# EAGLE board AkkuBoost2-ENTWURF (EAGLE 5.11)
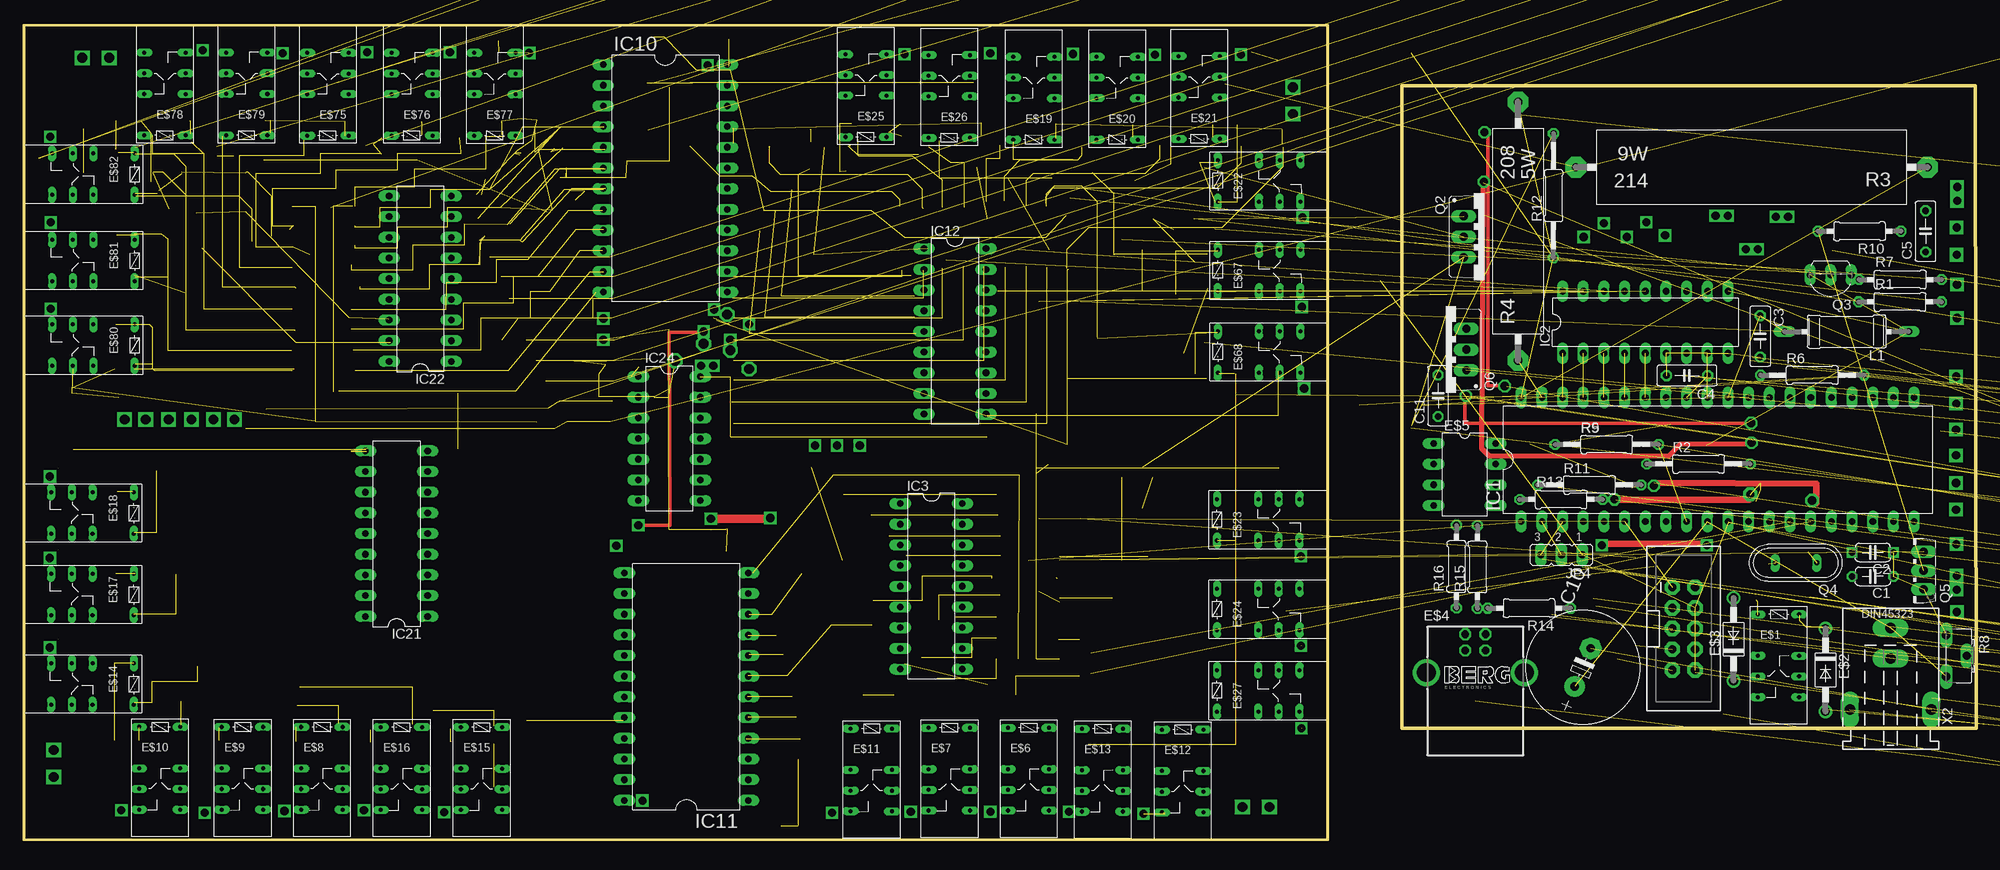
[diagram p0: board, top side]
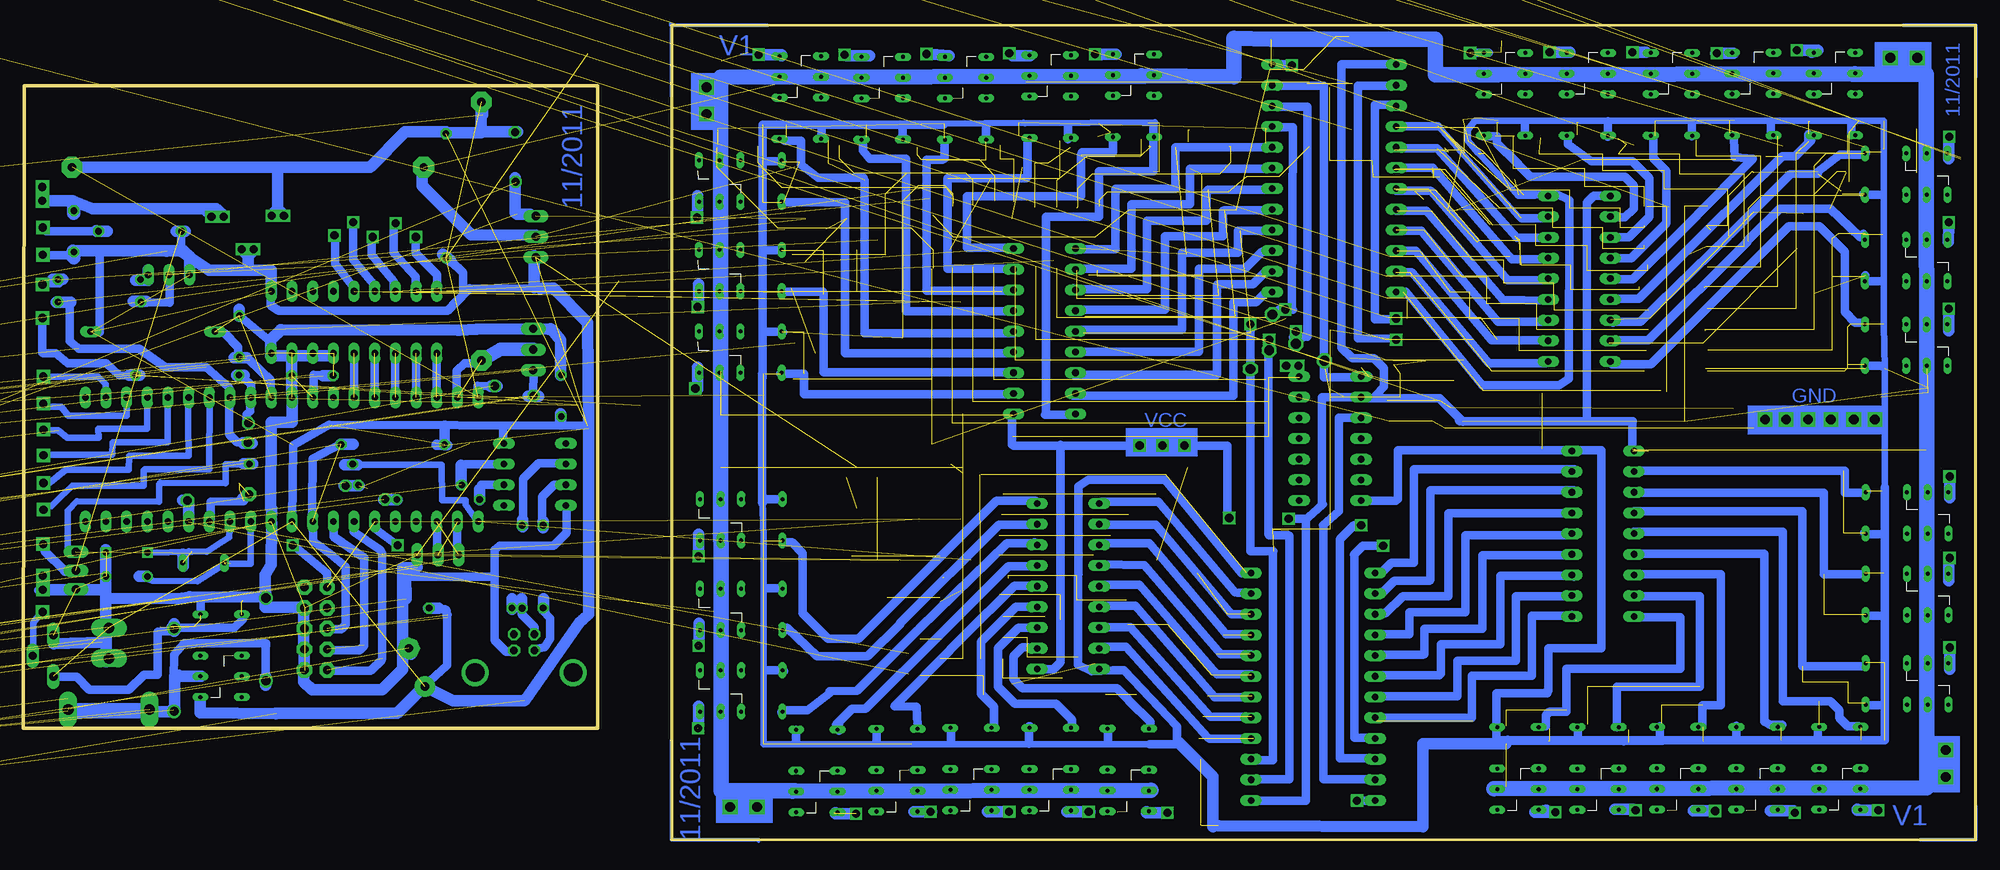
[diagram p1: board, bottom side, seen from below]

Size 239.82 x 100 mm. Coordinates in mm from the lower left corner, seen from the top.
Outline: 0.2,0 160.2,0 160.2,100
Outline: 0,0 0,100
Outline: 239.72,92.59 239.82,13.66 169.3,13.66 169.3,92.59 239.72,92.59
Outline: 0.1,100 160.1,100 160.1,0 0.1,0 0.1,100
Copper layers (1*16): Top 0.035mm / dielectric 1.5mm / Bottom 0.035mm
Design rules "default": minimum track width 10mil, minimum drill 24mil, track to track 8mil, track to pad 8mil, pad to pad 8mil, via to via 8mil, smd to smd 8mil, copper to edge 40mil, drill to drill 8mil, minimum pad ring 10mil, minimum via ring 8mil, stop-mask expansion 4mil, vias tented up to drill 0mil, thermal gap 10mil
tKeepout: 46 lines

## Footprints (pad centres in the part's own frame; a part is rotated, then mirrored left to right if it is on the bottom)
C050-024X044 = drill 0.813 octagon: 1 -2.54,0; 2 2.54,0
C050-025X075 = drill 0.813 octagon: 1 -2.54,0; 2 2.54,0
E5-13 = drill 1.016 pad 2.54 round: + -2.54,0 | drill 1.016 pad 2.54 octagon: - 2.54,0
2X5-SHROUDED_LOCK = drill 1.016 pad 1.88 octagon: 1 -1.397,5.08; 2 1.397,5.08; 3 -1.397,2.54; 4 1.397,2.54; 5 -1.397,0; 6 1.397,0; 7 -1.397,-2.54; 8 1.397,-2.54; 9 -1.397,-5.08; 10 1.397,-5.08
AXICOM-V23079-X1XXX-B301 = drill 0.5 long: 1 -6.45,-2.493; 3 -1.376,-2.493; 4 1.16,-2.493; 5 3.701,-2.493; 8 3.704,2.59; 9 1.16,2.59; 10 -1.369,2.59; 12 -6.45,2.59
DO41-10 = drill 1.118 round: A 5.08,0; C -5.08,0
PN61729-S = drill 0.95 octagon: 1 1.25,4.71; 2 -1.25,4.71; 3 -1.25,2.71; 4 1.25,2.71 | drill 2.3 pad 2.9 round: S1 -6.02,0; S2 6.02,0
DIL08 = drill 0.813 long: 1 -3.81,-3.81; 2 -1.27,-3.81; 3 1.27,-3.81; 4 3.81,-3.81; 5 3.81,3.81; 6 1.27,3.81; 7 -1.27,3.81; 8 -3.81,3.81
DIL40 = drill 0.813 long: 1 -24.13,-7.62; 2 -21.59,-7.62; 3 -19.05,-7.62; 4 -16.51,-7.62; 5 -13.97,-7.62; 6 -11.43,-7.62; 7 -8.89,-7.62; 8 -6.35,-7.62; 9 -3.81,-7.62; 10 -1.27,-7.62; 11 1.27,-7.62; 12 3.81,-7.62; 13 6.35,-7.62; 14 8.89,-7.62; 15 11.43,-7.62; 16 13.97,-7.62; 17 16.51,-7.62; 18 19.05,-7.62; 19 21.59,-7.62; 20 24.13,-7.62; 21 24.13,7.62; 22 21.59,7.62; 23 19.05,7.62; 24 16.51,7.62; 25 13.97,7.62; 26 11.43,7.62; 27 8.89,7.62; 28 6.35,7.62; 29 3.81,7.62; 30 1.27,7.62; 31 -1.27,7.62; 32 -3.81,7.62; 33 -6.35,7.62; 34 -8.89,7.62; 35 -11.43,7.62; 36 -13.97,7.62; 37 -16.51,7.62; 38 -19.05,7.62; 39 -21.59,7.62; 40 -24.13,7.62
DIL18 = drill 0.813 long: 1 -10.16,-3.81; 2 -7.62,-3.81; 3 -5.08,-3.81; 4 -2.54,-3.81; 5 0,-3.81; 6 2.54,-3.81; 7 5.08,-3.81; 8 7.62,-3.81; 9 10.16,-3.81; 10 10.16,3.81; 11 7.62,3.81; 12 5.08,3.81; 13 2.54,3.81; 14 0,3.81; 15 -2.54,3.81; 16 -5.08,3.81; 17 -7.62,3.81; 18 -10.16,3.81
DIL24-6 = drill 0.813 long: 1 -13.97,-7.62; 2 -11.43,-7.62; 3 -8.89,-7.62; 4 -6.35,-7.62; 5 -3.81,-7.62; 6 -1.27,-7.62; 7 1.27,-7.62; 8 3.81,-7.62; 9 6.35,-7.62; 10 8.89,-7.62; 11 11.43,-7.62; 12 13.97,-7.62; 13 13.97,7.62; 14 11.43,7.62; 15 8.89,7.62; 16 6.35,7.62; 17 3.81,7.62; 18 1.27,7.62; 19 -1.27,7.62; 20 -3.81,7.62; 21 -6.35,7.62; 22 -8.89,7.62; 23 -11.43,7.62; 24 -13.97,7.62
DIL14 = drill 0.813 long: 1 -7.62,-3.81; 2 -5.08,-3.81; 3 -2.54,-3.81; 4 0,-3.81; 5 2.54,-3.81; 6 5.08,-3.81; 7 7.62,-3.81; 8 7.62,3.81; 9 5.08,3.81; 10 2.54,3.81; 11 0,3.81; 12 -2.54,3.81; 13 -5.08,3.81; 14 -7.62,3.81
JP2 = drill 0.914 long: 1 -2.54,0; 2 0,0; 3 2.54,0
SMCC12 = drill 0.813 long: 1 -6.35,0; 2 8.89,0
TO220BV = drill 1.016 long: D 0,-2.54; G -2.54,-2.54; S 2.54,-2.54
TO92-EBC = drill 0.813 long: B 0,-1.27; C -2.54,-1.27; E 2.54,-1.27
QS = drill 0.61 long: 1 -2.54,0; 2 2.54,0
TO126AV = drill 1.016 long: B 2.286,-1.27; C 0,-1.27; E -2.286,-1.27
0207/10 = drill 0.813 octagon: 1 -5.08,0; 2 5.08,0
0207/12 = drill 0.813 octagon: 1 -6.35,0; 2 6.35,0
KH214-8 = drill 1.016 pad 2.54 octagon: 1 -21.59,0; 2 21.59,0
KH208-8 = drill 1.016 pad 2.54 octagon: 1 -15.875,0; 2 15.875,0
CA6H = drill 1.016 long: A -2.54,0; E 2.54,0; S 0,2.54
0207/15 = drill 0.813 octagon: 1 -7.62,0; 2 7.62,0
737992-5 = drill 1.3 pad 2.184 long: + 0,10; -1 5,0; -2 -5,0; K 0,6.25

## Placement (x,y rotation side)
C1  22p  [C050-024X044]  227.12,32.32 180 top
C2  22p  [C050-024X044]  227.12,35.25 180 top
C3  100n  [C050-025X075]  213.29,61.81 270 top
C4  100n  [C050-025X075]  204.3,56.98 180 top
C5  100n  [C050-025X075]  233.61,74.69 90 top
C10  1000µF  [E5-13]  191.48,21.16 67.2 top
C11  100n  [C050-025X075]  173.74,54.51 90 top
CON1  ISP  [2X5-SHROUDED_LOCK]  203.88,25.92 0 top
E$1  [AXICOM-V23079-X1XXX-B301]  215.47,21.22 270 top
E$2  1N4007  [DO41-10]  221.3,20.84 270 top
E$3  1N4007  [DO41-10]  210.01,24.6 90 top
E$4  [PN61729-S]  178.3,20.53 0 top
E$5  Attiny45  [DIL08]  176.99,44.85 270 top
E$6  [AXICOM-V23079-X1XXX-B301]  123.37,7.29 270 top
E$7  [AXICOM-V23079-X1XXX-B301]  113.64,7.29 270 top
E$8  [AXICOM-V23079-X1XXX-B301]  36.57,7.39 270 top
E$9  [AXICOM-V23079-X1XXX-B301]  26.84,7.39 270 top
E$10  [AXICOM-V23079-X1XXX-B301]  16.66,7.39 270 top
E$11  [AXICOM-V23079-X1XXX-B301]  104.06,7.19 270 top
E$12  [AXICOM-V23079-X1XXX-B301]  142.29,7.07 270 top
E$13  [AXICOM-V23079-X1XXX-B301]  132.45,7.16 270 top
E$14  [AXICOM-V23079-X1XXX-B301]  7.09,19.17 180 top
E$15  [AXICOM-V23079-X1XXX-B301]  56.19,7.37 270 top
E$16  [AXICOM-V23079-X1XXX-B301]  46.35,7.36 270 top
E$17  [AXICOM-V23079-X1XXX-B301]  7.09,30.17 180 top
E$18  [AXICOM-V23079-X1XXX-B301]  7.09,40.17 180 top
E$19  [AXICOM-V23079-X1XXX-B301]  124.13,92.41 90 top
E$20  [AXICOM-V23079-X1XXX-B301]  134.36,92.41 90 top
E$21  [AXICOM-V23079-X1XXX-B301]  144.44,92.51 90 top
E$22  [AXICOM-V23079-X1XXX-B301]  153.11,80.83 0 top
E$23  [AXICOM-V23079-X1XXX-B301]  153.01,39.23 0 top
E$24  [AXICOM-V23079-X1XXX-B301]  153.01,28.23 0 top
E$25  [AXICOM-V23079-X1XXX-B301]  103.51,92.73 90 top
E$26  [AXICOM-V23079-X1XXX-B301]  113.75,92.64 90 top
E$27  [AXICOM-V23079-X1XXX-B301]  153.01,18.23 0 top
E$67  [AXICOM-V23079-X1XXX-B301]  153.11,69.83 0 top
E$68  [AXICOM-V23079-X1XXX-B301]  153.11,59.83 0 top
E$75  [AXICOM-V23079-X1XXX-B301]  37.43,92.91 90 top
E$76  [AXICOM-V23079-X1XXX-B301]  47.76,92.91 90 top
E$77  [AXICOM-V23079-X1XXX-B301]  57.94,92.91 90 top
E$78  [AXICOM-V23079-X1XXX-B301]  17.41,92.93 90 top
E$79  [AXICOM-V23079-X1XXX-B301]  27.45,92.94 90 top
E$80  [AXICOM-V23079-X1XXX-B301]  7.19,60.77 180 top
E$81  [AXICOM-V23079-X1XXX-B301]  7.19,71.17 180 top
E$82  [AXICOM-V23079-X1XXX-B301]  7.19,81.77 180 top
IC1  MEGA32  [DIL40]  208.07,46.68 0 top
IC2  ULN2803  [DIL18]  199.19,63.54 0 top
IC3  ULN2803  [DIL18]  111.49,31.11 270 top
IC10  4514N  [DIL24-6]  78.8,81.21 270 top
IC11  4514N  [DIL24-6]  81.4,18.79 90 top
IC12  ULN2803  [DIL18]  114.39,62.41 270 top
IC21  ULN2803  [DIL18]  45.81,37.59 90 top
IC22  ULN2803  [DIL18]  48.71,68.89 90 top
IC24  4011N  [DIL14]  79.31,49.25 270 top
JP4  UserSwitch  [JP2]  188.89,34.99 180 top
L1  100µH  [SMCC12]  225.18,62.39 180 top
Q2  IRF5305  [TO220BV]  179.42,74.03 270 top
Q3  BC558A  [TO92-EBC]  221.93,68.09 180 top
Q4  8MHz  [QS]  217.68,33.99 180 top
Q5  BD139  [TO126AV]  232.08,33.04 90 top
Q6  IRL1004  [TO220BV]  174.65,60.19 90 top
R1  10k  [0207/10]  230.46,66.04 0 top
R2  1k  [0207/12]  205.71,46.14 0 top
R3  1R8  [KH214-8]  212.24,82.57 180 top
R4  R51  [KH208-8]  183.55,74.72 90 top
R5  10k  [0207/12]  194.43,48.54 0 top
R6  180  [0207/12]  219.69,57.04 0 top
R7  180  [0207/10]  230.49,68.78 0 top
R8  10k  [CA6H]  236.11,22.58 270 top
R9  10k  [0207/12]  194.43,48.54 0 top
R10  6  [0207/10]  225.49,74.72 180 top
R11  10k  [0207/12]  192.32,43.56 0 top
R12  500k  [0207/15]  187.89,79.08 90 top
R13  470  [0207/10]  188.85,41.77 0 top
R14  1k5  [0207/10]  184.89,28.43 180 top
R15  68  [0207/10]  178.55,33.5 90 top
R16  68  [0207/10]  175.98,33.52 90 top
X2  [737992-5]  229.3,16 0 top

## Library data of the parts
C1-C5 C10 C11 R2 R5 R9 R11 = rcl
CON1 = SparkFun
E$1 E$6-E$27 E$67 E$68 E$75-E$82 = Relais
E$2 E$3 = ref-packages-longpad
E$4 = con-berg
E$5 = atmel
IC1 = atmel; OC_FARNELL: unknown; OC_NEWARK: unknown
IC2 IC3 IC12 IC21 IC22 = uln-udn
IC10 IC11 = 45xx
IC24 = 40xx
JP4 = jumper
L1 = inductors
Q2 Q5 Q6 = transistor-power
Q3 = transistor-pnp
Q4 = special
R1 R6 R7 R10 R12-R16 = resistor
R3 R4 = resistor-power; OC_FARNELL: unknown; OC_NEWARK: unknown
R8 = pot
X2 = con-conrad

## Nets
GND: C1.1 C2.1 C3.2 C4.2 CON1.4 CON1.6 CON1.8 CON1.10 IC1.11 IC1.31 IC2.6 IC2.7 IC2.8 IC2.9 JP4.1 Q5.E R8.A
N$1: Q2.G R1.2
N$2: C1.2 IC1.12 Q4.2
N$3: C2.2 IC1.13 Q4.1
N$4: R3.2
N$5: R6.1
N$6: Q3.B
N$8: R7.2
N$9: IC1.29 R6.2
N$10: IC1.40 R3.1 R4.2 R12.1
N$11: IC1.39 R4.1
N$12: CON1.1 IC1.6
N$13: CON1.5 IC1.9 R5.2
N$16: R7.1
N$17: R8.S
N$18: IC1.1
N$19: Q5.B
N$20: IC1.26
N$22: IC1.22
N$23: IC1.27
N$24: IC1.25
N$25: IC1.24
N$26: Q5.C R10.2
N$27: R10.1
N$28: IC2.18
N$29: IC2.17
N$30: IC2.16
N$31: IC2.15
N$32: IC2.14
N$53: C3.1 IC1.30 L1.2
N$54: C4.1 IC1.32
N$55: IC1.2 JP4.2
N$56: IC1.3 JP4.3
N$57: IC1.15
N$58: IC1.14
N$75: CON1.9 IC1.7
N$76: CON1.7 IC1.8
N$114: IC1.23
N$119: C10.- X2.-1
PA2: IC1.38 IC2.1
PA3: IC1.37 IC2.2
PA4: IC1.36 IC2.3
PA5: IC1.35 IC2.4
PA6: IC1.34 IC2.5
S$173: IC1.28
S$187: Q2.D
S$188: R1.1
S$189: Q3.C
VCC: C10.+ IC1.10 IC2.10 L1.1 Q2.S Q3.E R5.1 R8.E R12.2 X2.+

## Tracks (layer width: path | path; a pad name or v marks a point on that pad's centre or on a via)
GND  (via drill 0.8 pad 1.27)  (16 unrouted)
  Bottom 1.422: IC1.31 206.78,51.27 209.35,51.27 209.41,40.69 209.34,40.64 209.34,38.95 IC1.11
  other vias: 229.66,35.25
N$1  (2 unrouted)
N$2  (2 unrouted)
  Bottom 0.813: 214.33,33.89 211.88,33.89 IC1.12 | 215,33.89 218.38,31.72 223.94,31.77 225.55,32.33 225.6,32.33
  Bottom 1.422: 225.6,32.33 C1.2
N$3  (1 unrouted)
  Bottom 0.813: IC1.13 214.51,37.15 217.26,35.35 219.49,35.39 219.12,35.34 C2.2
N$4  (1 unrouted)
N$6  (1 unrouted)
N$7  (4 unrouted)
N$8  (1 unrouted)
N$9  (3 unrouted)
N$10  (4 unrouted)
N$11  (2 unrouted)
N$12  (2 unrouted)
N$13  (3 unrouted)
  Bottom 1.016: 200.22,26.38 200.19,33.55 202.14,35.08 204.22,36.65 IC1.9
N$18  (1 unrouted)
N$19  (1 unrouted)
N$21  (via drill 1 pad 1.68)
  other vias: 237.44,27.97
N$26  (1 unrouted)
N$28  (1 unrouted)
N$29  (1 unrouted)
N$30  (1 unrouted)
N$31  (1 unrouted)
N$32  (1 unrouted)
N$53  (3 unrouted)
N$54  (1 unrouted)
N$55  (1 unrouted)
N$56  (1 unrouted)
N$57  (1 unrouted)
N$58  (1 unrouted)
N$67  (2 unrouted)
N$68  (via drill 0.8 pad 1.27)
  other vias: 224.58,35.25
N$69  (via drill 1 pad 1.68)
  other vias: 237.41,30.71 237.41,32.41
N$71  (2 unrouted)
N$72  (6 unrouted)
N$73  (2 unrouted)
N$75  (2 unrouted)
  Bottom 1.016: 195.74,22.2 195.75,35.19 195.96,35.58 199.22,37.82 IC1.7
N$76  (2 unrouted)
  Bottom 1.016: 197.95,23.88 197.96,34.64 201.7,37.18 IC1.8
N$77  (2 unrouted)
  Bottom 1.422: 229.69,35.44 229.7,32.71
N$78
  Bottom 1.016: 196.61,38.99 196.61,38.5 196.6,38.18 193.95,36.19
N$80  (2 unrouted)
N$81  (1 unrouted)
  Bottom 1.422: 199.32,48.57 200.84,48.57
N$82
  Bottom 1.016: 200.76,48.62 204.29,46.75 204.33,40.86 204.38,39.19 204.3,39.12
N$83  (1 unrouted)
N$84  (4 unrouted)
N$85  (4 unrouted)
N$86  (8 unrouted)
N$87  (1 unrouted)
N$88  (2 unrouted)
N$90  (2 unrouted)
N$91  (2 unrouted)
N$92  (2 unrouted)
N$93  (2 unrouted)
N$94  (3 unrouted)
N$95  (1 unrouted)
N$96  (4 unrouted)
N$97  (5 unrouted)
N$98  (via drill 1 pad 1.68)
  other vias: 219.65,41.65
N$99  (via drill 1 pad 1.68)
  other vias: 212.07,42.43
N$100  (2 unrouted)
N$101
  Bottom 1.422: 220.24,41.68 219.5,41.66 219.48,39.17
N$102  (4 unrouted)
N$103  (6 unrouted)
N$104  (4 unrouted)
N$105  (2 unrouted)
N$106  (4 unrouted)
N$107  (2 unrouted)
N$108  (3 unrouted)
N$109  (3 unrouted)
  Bottom 1.016: 204.13,54.24 204.14,57.07
N$110  (1 unrouted)
N$111  (2 unrouted)
N$112  (2 unrouted)
N$113  (2 unrouted)
N$115  (11 unrouted)
N$116  (2 unrouted)
N$117  (1 unrouted)
N$118  (1 unrouted)
N$119  (1 unrouted)
N$120  (2 unrouted)
N$121  (3 unrouted)
  Bottom 1.93: 234.45,15.85 224.44,15.85 224.31,15.98
N$122  (1 unrouted)
N$123  (2 unrouted)
N$124  (2 unrouted)
N$125  (3 unrouted)
N$126  (2 unrouted)
N$127  (4 unrouted)
N$128  (11 unrouted)
N$129  (2 unrouted)
N$130  (4 unrouted)
N$131  (2 unrouted)
N$132  (4 unrouted)
N$133  (3 unrouted)
N$134  (2 unrouted)
N$135  (1 unrouted)
N$136  (2 unrouted)
N$137  (2 unrouted)
N$138  (via drill 1 pad 1.68)
  other vias: 237.39,36.29
N$139  (6 unrouted)
N$140
  Bottom 1.422: 220.17,33.59 220.18,34.99 220.22,35.02
N$141  (2 unrouted)
N$142  (4 unrouted)
  Bottom 1.016: 209.39,54.26 209.44,56.4 212.03,58.86
  Bottom 1.422: 212.36,59.16 213.93,59.15
N$143  (1 unrouted)
N$144  (1 unrouted)
N$145  (2 unrouted)
N$146  (via drill 1 pad 1.68)
  other vias: 237.33,40.53
N$147  (4 unrouted)
N$148  (2 unrouted)
N$149  (3 unrouted)
N$150  (4 unrouted)
N$151  (via drill 1 pad 1.68)
  other vias: 237.33,43.79
N$152  (via drill 1 pad 1.68)
  other vias: 237.34,47.19
N$153  (via drill 1 pad 1.68)
  other vias: 237.34,50.35 237.35,53.55
N$154  (via drill 1 pad 1.68)  (1 unrouted)
  other vias: 237.35,56.87 237.46,64.07 237.46,68.17 237.41,71.83 237.48,78.45 237.41,75.17 237.48,80.15
N$156  (1 unrouted)
  Bottom 1.422: 209.37,39.06 209.35,39.06
N$157
  Bottom 0.813: 238.62,22.48 238.62,26.66 237.55,28
N$158
  Bottom 1.422: 229.67,32.37 229.62,21.86
N$159  (3 unrouted)
  Bottom 1.422: 234.37,17.38 234.37,15.76
N$160  (2 unrouted)
  Bottom 1.422: 236.06,24.07 230.15,24.27 | 229.19,26.13 229.12,26.06
N$161  (2 unrouted)
PA2  (1 unrouted)
PA3  (1 unrouted)
PA4  (1 unrouted)
PA5  (1 unrouted)
PA6  (1 unrouted)
S$1  (1 unrouted)
S$2  (2 unrouted)
S$3  (5 unrouted)
S$4
  Bottom 0.813: 223.09,43.56 223.1,41.52 233.17,41.54
S$5
  Bottom 1.016: 233.46,30.7 229.77,30.7 229.67,30.6
S$6
  Bottom 1.016: 237.96,30.64 237.13,30.72 236.54,30.74 233.42,30.74 233.37,30.79
S$7
  Bottom 1.016: 237.27,36.29 237.19,35.4 234.79,33.06 234.74,32.92 232.91,32.92
S$8
  Bottom 0.813: 234.38,35.34 234.36,40.41 233.24,41.54
  Bottom 1.016: 233.25,35.27 233.58,35.27 234.38,35.34
S$9  (5 unrouted)
S$10
  Bottom 0.813: 216.95,54.3 216.96,45.48 224.9,45.5 225,45.39 225.01,43.46 233.81,43.45 235.88,41.45 236.39,40.91 237.71,40.89
  Bottom 1.016: 217.05,54.3 216.95,54.3
S$11
  Bottom 0.813: 219.54,54.26 219.54,50.78 219.52,47.13 226.83,47.12 226.86,45.45 234.58,45.45 236.54,43.85
S$12
  Bottom 0.813: 222.06,54.21 222.06,50.84 222.05,48.78 228.85,48.81 228.87,47.28 237.34,47.29
S$13  (2 unrouted)
  Bottom 0.813: 224.6,54.21 224.6,51.47 224.6,50.48 230.6,50.48 230.57,49.34 234.42,49.34 235.47,50.22
S$14
  Bottom 0.813: 227.14,53.46 227.14,52.05 233.31,52.03 234.32,52.03 235.13,53.15 236.9,53.19
  Bottom 1.016: 227.16,54.19 227.14,53.46
S$15
  Bottom 0.813: 237.3,50.28 235.53,50.28
S$16
  Bottom 0.813: 229.67,54.3 229.67,55.91 230.63,56.87 237.36,56.87
S$17  (2 unrouted)
S$18
  Bottom 0.813: 184,39.01 185.5,41.13 185.5,41.7 188.4,41.7 188.44,46.05 198.99,46.03
S$19
  Bottom 0.813: 211.52,46.08 214.94,46.08 214.94,43.8 222.98,43.81 223.12,43.67
S$20  (4 unrouted)
S$21
  Bottom 1.016: 213.58,57.02 213.08,57 212.59,56.61 211.83,55.85 211.81,54.05 211.84,54.02
S$22  (2 unrouted)
  Bottom 1.016: 225.42,56.99 228.03,57.01 229.63,58.48 234.36,58.51 235.85,59.74 237.35,59.74
S$23  (2 unrouted)
S$24  (1 unrouted)
  Bottom 1.016: 214.48,54.08 214.48,55.28 214.45,55.31 214.57,55.55 217.34,57.99
S$25  (1 unrouted)
  Bottom 1.016: 226.16,66 221.83,65.96 221.85,69.39 221.92,69.46
S$26  (3 unrouted)
S$27  (2 unrouted)
S$28  (1 unrouted)
  Bottom 1.016: 235.42,68.94 235.38,68.3 237.32,68.3 237.35,68.26
S$29
  Bottom 1.016: 216.7,62.25 215.1,62.2 213.4,60.5 213.4,59.15 213.36,59.12
S$30
  Bottom 1.016: 237.58,71.75 233.56,71.75 233.48,71.66
S$31
  Bottom 1.676: 233.66,72.2 233.69,71.5 233.65,71.45
S$32
  Bottom 1.676: 233.65,78.14 233.65,76.95 233.6,76.91
S$33
  Bottom 1.422: 219.4,69.21 219.4,71.62 220.11,72.34 233.73,72.34 233.77,72.38
S$34
  Bottom 1.422: 219.9,74.68 221.04,74.68 221.06,74.7
S$35
  Bottom 1.016: 230.59,74.72 236.98,74.72 237.42,75.16
  Bottom 1.422: 229.54,74.72 230.59,74.72 230.81,74.72 230.84,74.75
S$36
  Bottom 1.016: 220.39,74.73 220.39,72.69 220.14,72.44
S$37
  Bottom 1.422: 237.54,78.45 233.81,78.45 233.52,78.15
S$38  (3 unrouted)
  Bottom 1.422: 222.14,72.3 222.19,72.26
S$39  (2 unrouted)
S$40  (1 unrouted)
S$41  (2 unrouted)
S$42  (1 unrouted)
S$43  (1 unrouted)
S$44  (4 unrouted)
S$45  (1 unrouted)
  Bottom 1.016: 229.69,29.66 229.76,29.1
  Bottom 1.422: 219.5,29.78 220.86,29.57 229.69,29.66
S$46  (3 unrouted)
  Bottom 1.676: 221.39,15.93 221.33,15.87
S$47
  Bottom 1.422: 221.23,17.52 221.25,17.52 221.25,15.74 224.27,15.74 224.27,15.75
S$48
  Bottom 1.422: 217.99,20.06 221.24,20.06 221.24,15.83
S$49  (4 unrouted)
S$50  (4 unrouted)
S$51
  Bottom 1.422: 210.07,18.96 210.07,20.01 210.04,20.03
S$52
  Bottom 1.422: 210.07,30.37 210.07,29.05 210.09,29.02
S$53  (3 unrouted)
  Bottom 1.422: 210.01,29.78 219.37,29.8
S$54  (1 unrouted)
  Bottom 1.422: 218.09,17.26 218.09,15.76 218.11,15.56 208.73,15.48
S$55  (2 unrouted)
S$56  (1 unrouted)
  Bottom 1.422: 205.37,26.48 205.33,20.54
S$57
  Bottom 1.422: 205.29,28.54 210.09,28.54 210.11,30.09
S$58
  Bottom 1.422: 209.34,38.85 209.39,33.75 210.11,32.56 210.11,29.73
S$59  (2 unrouted)
S$60
  Bottom 1.422: 205.37,28.69 205.37,25.77 205.32,25.72
S$61  (2 unrouted)
S$62
  Bottom 1.016: 202.71,23.23 198.51,23.23 197.96,23.79
S$63
  Bottom 1.016: 202.61,25.84 200.75,25.84 200.21,26.37
S$64
  Bottom 1.016: 202.64,20.73 197.13,20.73 195.81,22.04
S$65  (via drill 1)
  other vias: 206.74,36.16
S$66  (via drill 1)
  other vias: 193.82,36.16
S$67
  Top 0.813: 193.81,36.32 206.71,36.32 206.75,36.27
S$68
  Bottom 1.016: 202.53,30.94 202.48,32.7 206.75,36.2
S$69  (1 unrouted)
  Bottom 1.422: 205.37,20.74 205.37,19.42 204.33,18.38 195.75,18.38 193.21,20.92 193.25,33.41
S$70  (2 unrouted)
  Bottom 1.422: 191.47,33.44 193.18,33.41
S$71  (1 unrouted)
  Bottom 1.016: 186.56,38.99 186.54,38.21 186.54,35.46 186.54,34.49
S$72
  Bottom 1.016: 188.98,38.95 188.98,37.59 188.96,34.71
S$73
  Bottom 1.016: 221.56,25.74 221.06,25.59 223.33,25.56 223.33,20.22 224.97,20.22 226.84,18.43 231.7,18.43 233.28,20.01 235.99,20.01 236.05,19.95
S$74
  Bottom 1.422: 208.81,15.52 193.91,15.52 190.49,18.94
S$75
  Bottom 1.422: 192.19,22.79 192.19,23.74 192.48,24.04
S$76
  Bottom 1.016: 210.05,19.59 210.02,23.24 210,24.11 220.06,24.11 221.3,22.72 221.31,19.87 220.64,20.38
S$77
  Bottom 1.422: 198.73,46.07 200.36,46.07
S$78  (1 unrouted)
  Bottom 1.422: 211.64,46.16 212.75,46.15
S$79
  Bottom 1.27: 187.74,48.46 189.07,48.47
S$80
  Bottom 1.27: 188.07,48.46 188.06,50.83
S$81  (3 unrouted)
  Bottom 1.016: 193.11,28.66 193.14,28.69
S$82  (1 unrouted)
S$83  (1 unrouted)
  Bottom 1.422: 192.81,29.57 192.84,32.4
S$84  (6 unrouted)
  Bottom 1.016: 187.74,27.34 187.76,21.45 190.6,18.81
S$85  (1 unrouted)
  Bottom 1.422: 193.87,41.77 195.56,41.77
S$86  (2 unrouted)
S$87  (6 unrouted)
S$88  (3 unrouted)
  Bottom 1.016: 212.75,41.56 216.81,41.5 216.81,39.36 216.85,39.31
S$89
  Bottom 1.422: 212.08,42.51 212.94,41.81 211.99,42.56
S$90  (via drill 1)
  other vias: 200.22,43.46
S$91  (1 unrouted)
S$92  (2 unrouted)
S$93  (1 unrouted)
  Bottom 1.422: 200.44,43.49 198.56,43.49
S$94  (1 unrouted)
  Bottom 1.422: 186.06,45.95 186.02,43.55 | 183.75,41.76 183.75,43.02
S$95  (6 unrouted)
S$96  (via drill 1)
  other vias: 195.37,41.78
S$97  (1 unrouted)
  Top 0.813: 220.17,41.67 220.2,41.3 220.2,43.71 200.31,43.81 | 211.97,41.77 195.41,41.71
S$98  (2 unrouted)
S$99  (2 unrouted)
S$100  (2 unrouted)
S$101  (2 unrouted)
S$102  (2 unrouted)
S$103  (1 unrouted)
S$104  (2 unrouted)
S$105  (2 unrouted)
S$106  (2 unrouted)
S$107  (2 unrouted)
S$108  (2 unrouted)
S$109  (4 unrouted)
S$110  (4 unrouted)
S$111  (2 unrouted)
S$112
  Bottom 1.016: 173.1,40.8 173.1,37.7 174.7,36.1 181.3,36.1 181.9,35.6 181.9,32.3 192.9,32.3 193,32.4
S$113  (via drill 1)
  other vias: 181.9,55.7
S$114  (1 unrouted)
S$115
  Bottom 1.422: 182.4,55.7 181.6,55.7
S$116  (8 unrouted)
S$117  (3 unrouted)
  Bottom 1.422: 190.48,18.81 190.48,18.75 187.02,17.09 178.3,17.09
S$118  (6 unrouted)
  Bottom 1.422: 202.98,56.97 201.75,56.97
S$119  (4 unrouted)
S$120
  Bottom 1.016: 213.38,64.38 209.48,61.21 209.43,59.59 209.35,59.6 209.48,59.48
S$121
  Bottom 1.016: 204.16,57.02 203.35,57.02 203.3,56.98
S$122
  Bottom 1.422: 209.41,59.41 201.91,59.41 201.89,59.44
S$123
  Bottom 1.422: 206.87,59.42 206.87,54.69
S$124  (2 unrouted)
S$125
  Bottom 1.016: 189,59.69 189.02,59.69 189.02,53.81
S$126
  Bottom 1.016: 191.56,59.75 191.58,59.75 191.58,54.2
S$127
  Bottom 1.016: 194.11,59.75 194.15,59.75 194.15,54.06
S$128
  Bottom 1.016: 196.66,54.22 196.63,54.22 196.63,59.99
S$129
  Bottom 1.016: 199.22,59.79 199.2,59.79 199.2,54.14
S$130
  Bottom 1.422: 213.31,65.1 213.31,64.28
S$131
  Bottom 1.422: 220.36,72.19 217,69.9 209.38,69.9 209.38,67.12
S$132  (6 unrouted)
S$133  (3 unrouted)
  Bottom 1.016: 221.71,26.14 221.73,26.13
S$134  (2 unrouted)
S$135
  Bottom 1.016: 183.69,58.51 185.62,58.51 186.58,57.56 186.58,54.09 186.51,54.02
S$136  (2 unrouted)
S$137  (via drill 1)
  other vias: 212.16,51.16
S$138  (via drill 1)
  other vias: 177.15,54.51
S$139  (1 unrouted)
  Top 0.406: 212.26,51.16 177,51.16 177,54.49 177,54.45
S$140
  Bottom 1.016: 211.94,54.26 211.94,52.62 212.35,52.21 212.35,51.13 212.18,50.95
S$141  (1 unrouted)
  Bottom 1.016: 177.22,54.46 177.16,57.73
S$142
  Bottom 1.016: 209.44,66.93 209.44,65.62 208.46,64.97 187.73,64.97 186.58,66.09
S$143
  Bottom 1.422: 209.46,60.06 209.42,61.37 208.12,62.6
S$144
  Bottom 1.016: 186.39,62.57 186.27,62.57
  Bottom 1.422: 208.18,62.6 186.39,62.57 | 186.27,62.57 184.12,62.67 175.04,62.72
S$145  (1 unrouted)
  Bottom 1.422: 176.54,54.44 177.78,54.43
S$146
  Bottom 1.676: 177.19,60.2 181.22,60.2 183.92,58.63
S$147  (2 unrouted)
S$148  (5 unrouted)
  Bottom 1.016: 183.99,54.25 184,55.73 182.44,55.66 182.19,55.66
S$149  (4 unrouted)
S$150  (2 unrouted)
S$151  (8 unrouted)
S$152  (2 unrouted)
S$153  (4 unrouted)
S$154  (4 unrouted)
S$155  (via drill 1)
  other vias: 212.22,48.73
S$156
  Bottom 1.016: 214.56,54.09 214.56,49.76 213.56,48.77 212.26,48.77 212.17,48.68
S$157
  Bottom 1.422: 211.7,48.68 212.78,48.68 212.83,48.73
S$158  (via drill 1)
  other vias: 179.35,80.79
S$159  (3 unrouted)
  Top 0.61: 212.36,48.54 203.38,48.54 202.02,47.05 180,47.1 179.08,48.02 179.28,80.65
S$160  (6 unrouted)
S$161  (1 unrouted)
  Bottom 1.422: 177.56,76.8 179.17,76.8
S$162
  Bottom 1.016: 176.78,67.62 185.02,67.69 186.82,65.83
S$163  (2 unrouted)
S$164  (8 unrouted)
S$165  (via drill 1)
  other vias: 179.43,86.87
S$166  (1 unrouted)
S$167
  Top 0.406: 179.85,87.2 179.85,55.76 181.8,55.72
S$168  (2 unrouted)
S$169  (2 unrouted)
S$170  (2 unrouted)
S$171  (6 unrouted)
S$172  (2 unrouted)
S$173  (1 unrouted)
S$174  (4 unrouted)
S$175  (1 unrouted)
  Bottom 0.813: 14.16,12.23 14.29,12.23
S$176  (1 unrouted)
S$177  (1 unrouted)
  Bottom 0.813: 23.94,12.23 24.06,12.23
S$178  (1 unrouted)
S$179
  Bottom 1.93: 59.21,6.26 6,6.39
S$180  (via drill 1)
  Bottom 1.422: 34.7,3.52 v32.03,3.52
S$181  (via drill 1)
  other vias: 22.25,3.32
S$182  (2 unrouted)
S$183  (via drill 1)
  Bottom 1.422: 14.54,3.72 14.54,3.6 v12,3.6
S$184  (3 unrouted)
S$185  (3 unrouted)
S$186  (via drill 1)
  other vias: 3.22,44.6 3.22,23.6 3.22,34.6
S$187  (1 unrouted)
S$188  (1 unrouted)
S$189  (1 unrouted)
S$190
  Bottom 1.422: 25.22,3.52 22.42,3.52
S$191  (1 unrouted)
S$192  (1 unrouted)
S$193  (1 unrouted)
S$194  (1 unrouted)
S$195  (1 unrouted)
S$196  (2 unrouted)
S$197  (1 unrouted)
S$198  (1 unrouted)
S$199  (1 unrouted)
S$200  (1 unrouted)
S$201  (1 unrouted)
S$202  (2 unrouted)
S$203  (via drill 1)
  Bottom 1.422: 52.77,3.6 54.17,3.37 v51.63,3.37
S$204  (via drill 1)
  other vias: 41.78,3.62
S$205
  Bottom 1.422: 44.31,3.72 42.16,3.72
S$206  (1 unrouted)
  Bottom 0.813: 43.24,11.98 33.46,12.11
S$207
  Bottom 1.016: 84.4,37.4 86.8,37.4
S$208  (6 unrouted)
S$209  (3 unrouted)
S$210  (5 unrouted)
S$211  (4 unrouted)
S$212  (6 unrouted)
S$213  (1 unrouted)
S$214  (4 unrouted)
S$215  (2 unrouted)
S$216  (2 unrouted)
S$217  (6 unrouted)
S$218  (6 unrouted)
S$219  (11 unrouted)
S$220  (3 unrouted)
S$221  (3 unrouted)
S$222  (3 unrouted)
S$223  (4 unrouted)
S$224  (1 unrouted)
S$225
  Bottom 1.016: 86.9,37.5 86.9,61.6 87,61.6
S$226
  Bottom 1.016: 77.9,60.6 77.9,60.4 76.6,59.1 73.9,59.1 72.7,57.9 72.7,55.6 73.7,54.6
S$227  (4 unrouted)
S$228
  Bottom 1.016: 75.5,54.2 65.8,54.2
S$229  (1 unrouted)
S$230  (1 unrouted)
S$231  (4 unrouted)
S$232  (1 unrouted)
S$233
  Bottom 1.016: 88.9,4.78 82.3,4.78 82.3,39.28
S$234
  Bottom 1.016: 89.03,7.45 84.33,7.45 84.33,37.35
S$235
  Bottom 1.016: 88.9,9.73 86.36,9.73 86.36,35.42
S$236  (3 unrouted)
S$237
  Bottom 1.016: 74.04,7.45 80.14,7.45 80.14,38.65
S$238  (1 unrouted)
  Bottom 0.813: 146.04,87.77 145.91,87.77
S$239  (1 unrouted)
  Bottom 0.813: 136.26,87.77 136.13,87.77
S$240
  Bottom 1.93: 102.19,93.74 154.2,93.61
S$241  (via drill 1)
  Bottom 1.422: 126.1,96.28 v128.87,96.48
S$242  (via drill 1)
  other vias: 138.95,96.38
S$243  (via drill 1)
  Bottom 1.422: 146.66,96.28 146.66,96.4 v149.5,96.4
S$244  (via drill 1)
  other vias: 157.28,55.4 157.08,76.4 156.98,65.4
S$245
  Bottom 1.422: 135.88,96.28 138.68,96.28
S$246  (2 unrouted)
S$247  (4 unrouted)
S$248  (2 unrouted)
S$249  (2 unrouted)
S$250  (1 unrouted)
S$251
  Bottom 0.813: 116.8,88 100.8,88.1
S$252
  Bottom 0.406: 0,93.6 0,100 8.9,100
S$253  (via drill 1)
  Bottom 1.422: 107.43,96.4 105.63,96.43 v108.17,96.43
S$254  (via drill 1)
  other vias: 118.72,96.58
S$255  (9 unrouted)
  Bottom 1.016: 118.5,54.7 143.9,54.7 143.9,57.2 146.7,57.2 | 146.5,62.3 146.6,62.4 | 146.6,62.3 146.6,62.4 | 146.6,62.4 148.9,62.4
S$256
  Bottom 1.422: 116.19,96.28 118.34,96.28
S$257  (3 unrouted)
S$258  (1 unrouted)
S$259  (1 unrouted)
S$260  (5 unrouted)
S$261  (5 unrouted)
S$262  (5 unrouted)
S$263  (5 unrouted)
S$264  (3 unrouted)
S$265  (5 unrouted)
S$266  (6 unrouted)
S$267  (6 unrouted)
S$268  (7 unrouted)
S$269  (1 unrouted)
S$270  (2 unrouted)
  Bottom 0.813: 116.96,88.02 126.74,87.89
S$271  (via drill 1)
  other vias: 84,95.1
S$272  (via drill 1)
  Bottom 1.016: 83.3,56.8 83.3,58.1 v83.2,58.2 84.8,58.2
  other vias: 84.7,58.2
S$273
  Bottom 1.016: 86.6,64.5 86.2,64.5 85.6,65.1
S$274  (via drill 1)
  Bottom 1.016: 73.8,4.8 v76,4.8
S$275
  Bottom 1.016: 86.6,95.2 83.9,95.2
S$276
  Bottom 1.016: 72.8,36.1 75.3,36.1 76.4,35
S$277  (2 unrouted)
  Bottom 1.016: 42.2,48 42.2,51.4
S$278  (3 unrouted)
S$279  (3 unrouted)
S$280
  Bottom 1.016: 93.6,1.9 93.6,7.7 97.9,12
S$281
  Bottom 1.016: 110.5,52.2 114.3,52.2
S$282  (via drill 1)
  other vias: 84.4,39.4
S$283
  Bottom 1.016: 84.5,39.4 82.2,39.4
S$284  (via drill 1)
  other vias: 91.7,39.5
S$285
  Top 1.016: 84.5,39.4 91.9,39.4
S$286  (via drill 1)
  Bottom 1.016: 118.2,48.4 v102.7,48.4 v99.9,48.4 v97.2,48.4 91.9,48.4 91.9,39.4
S$287  (1 unrouted)
  Bottom 1.016: 217.4,58 222.4,58 225.6,60.3 233,60.3
S$288
  Bottom 1.422: 236.2,68.8 235,68.8
S$289
  Bottom 1.422: 224.5,70 224.5,68.7 226,68.7
S$290
  Bottom 1.422: 226.3,66.1 224.7,66.1
S$291
  Bottom 1.016: 234.1,66 234.1,61.2 233.1,60.4
  Bottom 1.422: 234,66 234.1,66 235.8,66
S$292
  Bottom 1.422: 226.8,57 225.5,57
S$293
  Bottom 1.422: 212.7,57 213.6,57
S$294
  Bottom 1.016: 230.4,72 230.4,62.3 232.1,62.3
S$295
  Bottom 1.016: 237.5,64.1 237.5,59.8
S$296
  Bottom 1.422: 237.4,32.4 237.4,30.7 229.8,30.7
S$297
  Bottom 1.422: 229.7,30.8 229.7,35.6
S$298
  Bottom 1.422: 237.4,80.2 237.4,78.4
S$299
  Bottom 1.016: 187.4,71.2 187.3,71.1 185.8,69.6 185.8,67.2
  Bottom 1.422: 187.3,71.1 188.3,71.9
S$300
  Bottom 1.422: 177.1,71.7 177.1,67.8
S$301  (9 unrouted)
S$302
  Bottom 1.422: 187.8,86.8 183.6,86.8 183.6,90.7
S$303
  Bottom 1.422: 190.8,82.6 190.8,80.3 184.8,74.3 176.9,74.2
S$304  (1 unrouted)
S$305  (1 unrouted)
S$306
  Bottom 1.016: 181,48.7 180.9,48.7 180.9,50.7
S$307
  Bottom 1.016: 180.8,43.6 183.6,43.6 183.6,42.9
S$308
  Bottom 1.016: 180.8,46.1 185.5,46.1
S$309
  Bottom 1.016: 173.2,46.2 176.5,46.2 178.4,44.3 178.4,38.7
S$310
  Bottom 1.016: 173.3,43.6 174.6,43.6 176.1,42.1 176.1,38.6
S$311
  Bottom 1.422: 178.5,39.3 178.5,38.4
S$312
  Bottom 1.422: 176,39.1 176,38.3
S$313
  Bottom 1.422: 178.6,29.6 178.6,28.4
S$314
  Bottom 1.422: 175.9,29.6 175.9,28.3
S$315
  Bottom 1.016: 177,25 177,26.1 178.6,27.7 178.6,28.3
S$316
  Bottom 1.016: 177.1,23.4 175.8,23.6 175.1,24.7 175.1,27.2 176,28.1
S$317  (2 unrouted)
S$318
  Bottom 1.016: 179.7,23.1 180.5,23.1 181.9,24.5 181.9,32.3
S$319  (2 unrouted)
  Bottom 1.016: 187.7,27.6 187.8,27.5
S$320
  Bottom 1.422: 173.8,52.3 173.8,51.1
S$321
  Bottom 1.422: 173.8,57 173.8,61.3 174.9,62.7 175.3,62.7
S$322
  Bottom 1.422: 179.8,29.6 179.8,28.3
S$323
  Bottom 1.422: 188.8,28.4 190,28.4
S$324
  Bottom 1.016: 187.8,27.6 187.8,28.1 188,28.3 188.9,28.3
S$325  (1 unrouted)
S$326
  Bottom 1.422: 171.5,26.7 178.2,17.1
S$327
  Bottom 1.422: 179.4,81.3 179.4,77 179.3,76.9
S$328  (2 unrouted)
  Bottom 1.422: 176.4,67.7 174.7,67.7 170.5,63.5 170.4,50.5 170.4,27.7 171.1,27
S$329
  Bottom 1.422: 187.9,86.9 192.9,86.9 197.2,82.6 234.1,82.6 234.2,82.7
S$330  (1 unrouted)
  Bottom 1.422: 183.4,89 183.4,90.4
S$331
  Bottom 1.422: 183.8,86.9 179.1,86.9
S$332  (via drill 1)
  other vias: 191.6,74
S$333  (via drill 1)
  other vias: 194.1,75.7
S$334  (via drill 1)
  other vias: 196.9,74
S$335  (9 unrouted)
S$336  (via drill 1)
  other vias: 199.3,75.8
S$337  (via drill 1)
  other vias: 201.6,74.2
S$338  (via drill 1)
  Bottom 1.422: 208.6,82.4 208.6,77.4 v207.8,76.6 209.3,76.6 209.4,76.7 209.3,76.7 208.7,77.3
S$339  (via drill 1)
  other vias: 209.3,76.6
S$340
  Bottom 1.016: 191.6,73.8 191.6,72 189,69.4 189,67.6
S$341
  Bottom 1.016: 191.6,67.3 191.6,69.1 194.3,72.1 194.3,75.8
S$342
  Bottom 1.016: 194.3,67.6 194.3,68.6 197,71.8 197,73.9
S$343
  Bottom 1.016: 196.8,67.4 196.8,68.2 199.3,71.2 199.3,75.6 199.2,75.7
S$344
  Bottom 1.016: 199.2,67.6 199.3,67.9 201.5,70.7 201.5,74.1
S$345  (via drill 1)
  other vias: 215.2,76.5
S$346  (via drill 1)
  other vias: 216.7,76.5
S$347
  Bottom 1.422: 237.6,78.5 233.6,78.4 231.3,77.5 216.1,77.5 215.2,76.6 216.7,76.6 217.2,77.1
S$348
  Bottom 1.016: 212.9,27.6 212.9,27 213.9,26 221.3,26
S$349
  Bottom 1.016: 218,27.6 218,29.6
S$350
  Bottom 1.422: 221.3,25.6 221.3,26.5
S$351  (5 unrouted)
S$352
  Bottom 1.016: 13.5,58.2 11.5,58.2 11.4,58.1
S$353  (3 unrouted)
S$354
  Bottom 1.016: 11.4,79.2 13.6,79.2
S$355  (3 unrouted)
S$356
  Bottom 1.016: 15.3,86.5 15.3,88
S$357
  Bottom 1.016: 45.1,79.1 46.9,79.1 47.8,78.2 47.8,51.5
S$358  (6 unrouted)
S$359  (1 unrouted)
  Bottom 1.016: 56.2,79.2 54.2,79.2 51.6,79.3 49.9,78.5 50,56.6 51.2,55.8 60.6,55.8 70,67.3
S$360
  Bottom 1.016: 42.1,51.4 63.4,51.4 63.5,51.5
S$361
  Bottom 1.016: 25.2,88.1 25.2,86.5
S$362
  Bottom 1.016: 34.9,88.1 34.9,86.4
S$363
  Bottom 1.016: 45.2,88.2 45.2,86.3
S$364
  Bottom 1.016: 55.4,86.5 55.4,88
S$365
  Bottom 1.016: 58.8,86.4 58.8,85.5 57.6,84.3
S$366
  Bottom 1.016: 43.8,76.4 43.1,76.4 42,77.5 42,80.3 43.1,81.4 54.7,81.4 57.5,84.2
S$367
  Bottom 1.016: 50.1,86.2 50.1,85.4 47.2,83.3 42.2,83.3 40.1,81.2 40.1,76.5 42.6,74 45,74 45.1,73.9
S$368  (4 unrouted)
  Bottom 1.016: 52.4,76.3 55.8,76.3
S$369  (2 unrouted)
  Bottom 1.016: 52.6,73.9 56.4,73.9 66.1,84.8
S$370  (2 unrouted)
  Bottom 1.016: 52.5,71.3 57,71.3 66.6,82.4 | 66.7,82.5 70.5,82.5 71,82.7
S$371
  Bottom 1.016: 52.5,68.7 57.5,68.7 66.9,79.6
S$372  (2 unrouted)
  Bottom 1.016: 67,79.7 71.2,79.7
S$373
  Bottom 1.016: 52.7,66.2 58.1,66.3 67.5,77.2
S$374  (4 unrouted)
S$375  (4 unrouted)
S$376  (6 unrouted)
S$377  (3 unrouted)
S$378  (2 unrouted)
S$379  (3 unrouted)
S$380  (3 unrouted)
S$381  (2 unrouted)
S$382  (2 unrouted)
S$383  (2 unrouted)
S$384  (6 unrouted)
S$385  (4 unrouted)
S$386  (4 unrouted)
S$387  (4 unrouted)
S$388  (4 unrouted)
S$389  (4 unrouted)
S$390  (4 unrouted)
S$391  (3 unrouted)
S$392  (4 unrouted)
S$393  (2 unrouted)
S$394  (4 unrouted)
S$395  (2 unrouted)
S$396  (8 unrouted)
S$397  (1 unrouted)
S$398  (5 unrouted)
S$399  (1 unrouted)
S$400  (2 unrouted)
S$401  (2 unrouted)
S$402  (2 unrouted)
S$403  (2 unrouted)
S$404  (2 unrouted)
S$405  (2 unrouted)
S$406  (2 unrouted)
S$407  (2 unrouted)
S$408
  Bottom 1.016: 53,63.6 58.7,63.6 68,74.6
S$409
  Bottom 1.016: 52.6,61.3 59.5,61.3 68.8,72.3
S$410
  Bottom 1.016: 52.8,58.5 59.8,58.5 69.2,69.6
S$411
  Bottom 1.422: 157,58 157,55.3
S$412  (1 unrouted)
S$413  (5 unrouted)
S$414
  Bottom 1.016: 71.3,95.22 77.9,95.22 77.9,60.52
S$415
  Bottom 1.016: 71.17,92.55 75.87,92.55 75.87,61.65
S$416
  Bottom 1.016: 71.3,90.27 73.84,90.27 73.84,63.98
S$417
  Bottom 1.016: 86.16,92.55 80.06,92.55 80.06,60.55
S$418
  Bottom 1.016: 86.41,90.01 82.09,90.01 82.09,61.78
S$419
  Bottom 1.016: 86.54,87.47 83.87,87.47 83.97,65.08
S$420
  Bottom 1.016: 71.2,77.2 67.6,77.2
S$421
  Bottom 1.016: 68.1,74.8 71.1,74.8
S$422
  Bottom 1.016: 71.2,72.3 68.9,72.3
S$423
  Bottom 1.016: 71.2,69.7 69.3,69.7 69.2,69.6
S$424
  Bottom 1.016: 44.6,71.4 42.3,71.4 38,75.7 38,82.1 39.6,83.7 39.6,86
S$425
  Bottom 1.016: 44.9,68.8 42.1,68.8 35.8,75.1 29.5,81.5 27.4,83.6 29.6,83.8 29.7,86
S$426  (1 unrouted)
  Bottom 1.016: 44.8,66.4 41.4,66.4 33.1,74.7 23.8,83.9 22.2,83.9 20.2,85.9
S$427  (3 unrouted)
S$428  (2 unrouted)
S$429  (5 unrouted)
  Bottom 1.016: 13.7,84.1 16.7,84.1 19.4,82 | 30.4,74.1 41.2,63.6 44.4,63.6 44.6,63.5
S$430  (7 unrouted)
  Bottom 1.016: 13.9,74 14.2,74 17.9,77.5 | 28,73.5 40.2,61.3 44.5,61.3 44.6,61.2
S$431
  Bottom 1.016: 13.7,63.5 14.8,63.5 16.1,64.8 16.1,72.2 19.2,75.3 23,75.3 39.9,58.4 44.7,58.4 45,58.7
S$432
  Bottom 1.016: 17.9,77.5 24.1,77.5 28.1,73.5
S$433  (1 unrouted)
  Bottom 1.016: 30.3,74.3 30.2,74.3 22.8,81.7 19.4,81.8
S$434  (1 unrouted)
S$435
  Bottom 1.93: 145.31,5.96 101.3,6.09
S$436  (via drill 1)
  Bottom 1.422: 121.4,3.42 v118.73,3.42
S$437  (via drill 1)
  other vias: 108.95,3.42
S$438  (via drill 1)
  Bottom 1.422: 101.84,3.42 101.84,3.3 v99.3,3.3
S$439
  Bottom 1.422: 111.62,3.42 108.82,3.42
S$440  (via drill 1)
  Bottom 1.422: 140.07,3.3 140.07,3.17 v137.53,3.17
  other vias: 156.93,13.67
S$441  (via drill 1)
  other vias: 128.38,3.42
S$442
  Bottom 1.422: 130.41,3.42 128.26,3.42
S$443  (via drill 1)
  other vias: 156.88,34.8 156.88,23.8
S$444
  Bottom 1.93: 154.1,15.2 154.2,57.9
S$445
  Bottom 1.422: 156.9,16.4 156.9,13.7
S$446
  Bottom 1.422: 156.8,26.6 156.8,23.8
S$447
  Bottom 1.422: 156.9,37.5 156.9,34.8
S$448
  Bottom 1.016: 146.7,15.6 146.7,15.7
S$449
  Bottom 1.016: 146.4,25.7 146.4,25.6
S$450  (9 unrouted)
S$451
  Bottom 1.016: 146.4,20.7 146.5,20.8 146.5,20.7
S$452
  Bottom 1.016: 146.6,30.7 146.6,30.9 | 146.6,30.9 146.6,31 | 148.6,30.9 146.6,30.9
S$453
  Bottom 1.93: 145,6 154.1,6 154.1,15.7
S$454  (2 unrouted)
S$455
  Bottom 0.813: 149,42.2 148.9,36.7 148.9,11.7 101.8,11.7
S$456
  Bottom 1.016: 116.2,13.9 116.3,13.9
S$457
  Bottom 1.016: 139.6,13.4 139.6,14.3
S$458
  Bottom 1.016: 94.1,12.4 88.7,12.4
S$459
  Bottom 1.016: 89,15.1 94,15.1
S$460  (1 unrouted)
S$461
  Bottom 0.813: 149,42 149,41.3 149,39.9
  Bottom 1.016: 149.1,57.2 149.1,41.4 149,41.3
S$462  (via drill 1.2)
  other vias: 153,4
S$463  (via drill 1.2)
  other vias: 149.7,4
S$464
  Bottom 0.406: 160.2,6.4 160.2,0 151.3,0
S$465
  Bottom 1.016: 146.7,41.8 148.7,41.8 148.8,41.9
S$466
  Bottom 1.016: 148.8,20.8 146.6,20.8
S$467
  Bottom 1.016: 144.9,13.5 144.9,12
S$468
  Bottom 1.016: 115.1,20.9 113.3,20.9 112.4,21.8 112.4,48.5
S$469
  Bottom 1.016: 101.5,11.7 98.1,11.7 98.1,13.9 104.6,20.8
S$470
  Bottom 1.016: 104.6,20.8 106,20.8 108.6,20.7 110.3,21.5 110.2,43.4 109,44.2 99.6,44.2 90.2,32.7
S$471
  Bottom 1.016: 135,11.9 135,13.5
S$472
  Bottom 1.016: 125.9,12 125.9,13.7
S$473
  Bottom 1.016: 116.3,11.8 116.3,13.7
S$474
  Bottom 1.016: 106.6,13.5 106.6,12
S$475
  Bottom 1.016: 101.4,13.9 101.4,14.5 102.6,15.7
S$476
  Bottom 1.016: 116.4,23.6 117.1,23.6 118.2,22.5 118.2,19.7 117.1,18.6 105.5,18.6 102.7,15.8
S$477
  Bottom 1.016: 111,14 111,14.7 113,16.7 118,16.7 120.1,18.8 120.1,23.5 117.6,26 115.2,26 115.1,26.1
S$478
  Bottom 1.016: 107.8,23.7 104.4,23.7 94.3,12.5
S$479
  Bottom 1.016: 107.6,26.1 103.8,26.1 94.1,15.2
S$480
  Bottom 1.016: 107.7,28.7 103.2,28.7 93.6,17.6 | 93.5,17.5 89.7,17.5
S$481
  Bottom 1.016: 107.7,31.3 102.7,31.3 93.3,20.4
S$482
  Bottom 1.016: 93.2,20.3 89,20.3
S$483
  Bottom 1.016: 107.5,33.8 102.1,33.7 92.7,22.8
S$484
  Bottom 1.016: 107.2,36.4 101.5,36.4 92.2,25.4
S$485
  Bottom 1.016: 107.6,38.7 100.7,38.7 91.4,27.7
S$486
  Bottom 1.016: 107.4,41.5 100.4,41.5 91,30.4
S$487
  Bottom 1.016: 89,22.8 92.6,22.8
S$488
  Bottom 1.016: 92.1,25.2 89.1,25.2
S$489
  Bottom 1.016: 115.6,28.6 117.9,28.6 122.2,24.3 122.2,17.9 120.6,16.3 120.6,14
S$490
  Bottom 1.016: 115.3,31.2 118.1,31.2 124.4,24.9 130.7,18.5 132.8,16.4 130.1,16.3 130,14.1
S$491
  Bottom 1.016: 115.4,33.6 118.8,33.6 127.1,25.3 136.4,16.1 138,16.1 140,14.1
S$492
  Bottom 1.016: 146.5,15.9 143.5,15.9 140.8,18 | 129.8,25.9 119,36.4 115.8,36.4 115.6,36.5
S$493
  Bottom 1.016: 146.3,26 146,26 142.3,22.5 | 132.2,26.5 120,38.7 115.7,38.7 115.6,38.8
S$494
  Bottom 1.016: 146.5,36.5 145.4,36.5 144.1,35.2 144.1,27.8 141,24.7 137.2,24.7 120.3,41.6 115.5,41.6 115.2,41.3
S$495
  Bottom 1.016: 142.3,22.5 136.1,22.5 132.1,26.5
S$496
  Bottom 1.016: 129.9,25.7 130,25.7 137.4,18.3 140.8,18.2
S$497  (1 unrouted)
S$498  (1 unrouted)
S$499  (2 unrouted)
S$500  (1 unrouted)
S$501  (1 unrouted)
S$502  (1 unrouted)
S$503  (2 unrouted)
S$504
  Bottom 1.016: 89,30.3 90.7,30.3
S$505  (1 unrouted)
S$506
  Bottom 1.422: 93.7,1.6 93.7,7.7 98,12
S$507
  Bottom 1.016: 118.4,48.5 118.4,52.1
S$508
  Bottom 1.016: 89,27.7 91.4,27.7 91.6,27.9
S$509
  Bottom 1.016: 13.5,42.6 16.1,42.6 16.1,45.3
S$510
  Bottom 1.016: 13.5,37.5 11.6,37.5
S$511
  Bottom 1.016: 29.4,14 29.4,12.2
S$512
  Bottom 1.016: 38.8,13.9 38.8,12.3 38.9,12.2
S$513
  Bottom 1.016: 48.9,13.7 48.9,12.2
S$514
  Bottom 1.016: 58.9,13.6 58.9,12.2 57.5,12.3
S$515
  Bottom 1.016: 14.4,13.9 15.7,13.9 16.8,15 16.8,15.9 17.9,17 19.5,17
S$516
  Bottom 1.422: 154.2,56.8 154.2,57.2
  Bottom 1.93: 154.2,57.2 154.2,93.6
S$517
  Bottom 1.422: 156.9,68.2 156.9,65.4
S$518
  Bottom 1.422: 157,79.1 157,76.4
S$519  (2 unrouted)
  Bottom 1.016: 126.8,87.8 149,87.8 149,56.7
S$520  (1 unrouted)
  Bottom 1.016: 146.8,57.2 146.8,57.3
S$521  (1 unrouted)
  Bottom 1.016: 146.5,67.3 146.5,67.2
S$522  (2 unrouted)
S$523
  Bottom 1.016: 73.79,9.99 78.11,9.99 78.11,36.82
S$524  (4 unrouted)
S$525  (2 unrouted)
  Bottom 1.016: 118.2,57.4 141.5,57.4 141.5,67 141.6,67.3 146.6,67.3 | 146.7,72.3 146.7,72.4 | 146.7,72.4 146.7,72.6 | 146.7,72.4 148.7,72.4 148.9,72.2
S$526  (2 unrouted)
  Bottom 1.016: 118.2,59.7 138.9,59.7 138.9,78.3 146.4,78.3
S$527  (2 unrouted)
  Bottom 1.016: 118.2,62.2 136.5,62.2 136.5,81
S$528
  Bottom 1.016: 118.3,64.9 131.4,64.9 131.4,83.6
S$529  (2 unrouted)
  Bottom 1.016: 118.3,67.4 128.9,67.4 128.9,83.5 126.9,83.5 126.7,83.7 | 126.7,83.6 126.7,83.7 | 126.7,83.7 126.7,85.9
S$530  (2 unrouted)
  Bottom 1.016: 118.3,70.1 126.3,70.1 126.3,81.2
S$531  (2 unrouted)
  Bottom 1.016: 118.1,72.7 123.9,72.7 123.9,79 109.9,79 109.9,84.1
S$532
  Bottom 1.016: 73.66,12.53 76.33,12.53 76.33,35.02
S$533
  Bottom 1.422: 6,43.2 6,42.9
  Bottom 1.93: 6,42.9 6,6.4 | 6,55.6 6,43.2
S$534
  Bottom 1.422: 3.2,42 3.2,44.7
S$535
  Bottom 1.422: 3.3,31.8 3.3,34.6
S$536
  Bottom 1.422: 3.2,20.9 3.2,23.6
S$537  (2 unrouted)
  Bottom 0.813: 11.2,58 11.2,41
  Bottom 1.016: 33.4,12.2 19.4,12.2 | 19.4,12.2 11.2,12.2 11.2,16.5 | 11.2,16.5 11.2,41 11.2,43.3 | 13.5,16.5 11.2,16.5 | 19.4,13.7 19.4,12.2
S$538  (1 unrouted)
  Bottom 1.016: 13.4,42.8 13.4,42.7
S$539  (1 unrouted)
  Bottom 1.016: 13.7,32.7 13.7,32.8
S$540
  Bottom 1.016: 23.8,14.1 25.3,14.1 25.8,14.4
S$541
  Bottom 1.016: 44.1,13.8 44.1,18.8 33.9,18.8
S$542
  Bottom 1.016: 50.3,15.7 52.4,15.7 52.8,15.3 52.8,13.9
S$543
  Bottom 1.016: 33.7,12.2 58.2,12.2
S$544
  Bottom 1.016: 62.1,96.6 59.8,96.6
S$545
  Bottom 1.016: 60.6,86.4 58.9,86.4
S$546  (3 unrouted)
S$547
  Bottom 0.813: 56.1,76.5 56.2,76.5 66,87.6
S$548
  Bottom 1.016: 109.8,84.4 106,84.4 106,86.2
S$549
  Bottom 1.016: 101,87.8 101,86.3 101,82.1
S$550
  Bottom 1.016: 116.5,86.1 116.5,81.4
S$551
  Bottom 1.016: 111.5,86 111.5,87.7
S$552
  Bottom 1.016: 116.6,81.2 126.2,81.2
S$553
  Bottom 1.016: 121.6,86.2 121.6,87.7
S$554  (via drill 1)
  Bottom 1.422: 212.2,70 212.2,71.7 v213,72.5 211.5,72.5 211.4,72.4 211.5,72.4 212.1,71.8
S$555
  Bottom 1.016: 131.8,87.5 131.8,86 131.3,86
S$556
  Bottom 1.016: 146.6,83.3 148.9,83.3
S$557
  Bottom 1.016: 141.8,87.6 141.8,86.2
S$558
  Bottom 1.016: 136.6,81.3 142.2,81.3 144.3,82.9 144.3,85.8 146.3,85.8 146.5,86
S$559
  Bottom 1.016: 136.7,85.8 136.7,84.6 135.9,83.6 131.5,83.6
S$560  (via drill 1)
  other vias: 211.5,72.5
S$572  (1 unrouted)
  Bottom 1.016: 102.5,93.8 102.5,93.5
  Bottom 1.93: 66.4,98.3 86.6,98.3 91.1,98.4 91.1,93.7 102.5,93.8
S$573  (2 unrouted)
  Bottom 1.016: 86.5,85 98.3,85 | 111,72.6 111,72.7
S$574  (3 unrouted)
  Bottom 1.016: 86.5,82.4 96.5,82.4 96.5,78 103.7,78 103.7,70.1 110.7,70.1
S$575  (2 unrouted)
  Bottom 1.016: 86.5,79.8 94.3,79.8
S$576  (2 unrouted)
  Bottom 1.016: 86.4,77.3 92.3,77.3
S$577  (2 unrouted)
  Bottom 1.016: 86.5,74.8 90.4,74.8
S$578
  Bottom 1.016: 98.3,84.7 98.3,79.9 105.7,79.9 105.7,72.5 110.6,72.5 110.6,72.4
S$579
  Bottom 1.016: 94.5,79.6 94.5,76 101.8,76 101.8,67.6 110.8,67.6 110.8,67.7
S$580
  Bottom 1.016: 92.5,77.2 92.5,74.1 99.6,74.1 99.6,65.1 110.7,65.1
S$581
  Bottom 1.016: 90.6,74.8 90.6,72.1 97.5,72.1 97.5,62.6 110.9,62.6
S$582
  Bottom 1.016: 86.3,72.2 87.7,72.2 89.8,70.1 95.4,70.1 95.4,59.9 110.7,59.9
S$583
  Bottom 1.016: 86.5,69.7 87.3,69.7 88.8,68.2 93.1,68.2 93.2,68.1 93.2,57.1 110.8,57.1 110.8,57.2
S$584
  Bottom 1.016: 86.7,67.1 87.3,67.1 88.4,66 91.2,66 91.2,54.5 110.9,54.5 110.9,54.7
S$586  (3 unrouted)
  Bottom 1.016: 101,82.1 107.7,82.1 107.7,76.5 114.2,76.5 114.2,52.2
S$587
  Bottom 0.813: 43.4,12 58.3,12
S$588  (1 unrouted)
  Bottom 1.016: 6.1,47.9 6.1,42.5
S$589  (2 unrouted)
  Bottom 1.016: 41.7,45.3 16.3,45.3 | 13.7,37.7 13.6,37.6 13.6,37.7
S$590  (2 unrouted)
  Bottom 1.016: 42,42.6 18.7,42.6 18.7,32.6 13.5,32.6 | 13.5,27.7 13.5,27.5 | 13.5,27.5 13.5,27.4 | 13.5,27.5 11.4,27.5 11.3,27.4
S$591  (4 unrouted)
  Bottom 1.016: 42,40.3 21.3,40.3 21.3,21.3 13.8,21.3
S$592  (1 unrouted)
  Bottom 1.016: 42,37.8 23.7,37.8 23.7,17 19.3,17
S$593
  Bottom 1.016: 41.9,35.1 26,35.1 26,14.5
S$594  (2 unrouted)
  Bottom 1.016: 41.9,32.6 31.3,32.6 31.3,16.5 33.6,16.5 33.6,14
S$595  (2 unrouted)
  Bottom 1.016: 41.9,29.9 33.9,29.9 33.9,18.8
S$596  (2 unrouted)
  Bottom 1.016: 42.1,27.3 36.3,27.3 36.3,21 50.3,21 50.3,15.9
S$597  (2 unrouted)
S$598  (2 unrouted)
  Bottom 1.422: 93,1.7 67.9,1.6 67.9,11.8 57.7,11.8
S$599
  Bottom 1.016: 73.7,15 61.9,15 | 49.2,27.4 49.2,27.3
S$600
  Bottom 1.016: 73.7,17.6 63.7,17.6 63.7,22 56.5,22 56.5,29.9 49.5,29.9
S$601
  Bottom 1.016: 73.7,20.2 65.9,20.2
S$602
  Bottom 1.016: 73.8,22.7 67.9,22.7
S$603
  Bottom 1.016: 73.7,25.2 69.8,25.2
S$604
  Bottom 1.016: 61.9,15.3 61.9,20.1 54.5,20.1 54.5,27.5 49.6,27.5 49.6,27.6
S$605
  Bottom 1.016: 65.7,20.4 65.7,24 58.4,24 58.4,32.4 49.4,32.4 49.4,32.3
S$606
  Bottom 1.016: 67.7,22.8 67.7,25.9 60.6,25.9 60.6,34.9 49.5,34.9
S$607
  Bottom 1.016: 69.6,25.2 69.6,27.9 62.7,27.9 62.7,37.4 49.3,37.4
S$608
  Bottom 1.016: 73.9,27.8 72.5,27.8 70.4,29.9 64.8,29.9 64.8,40.1 49.5,40.1
S$609
  Bottom 1.016: 73.7,30.3 72.9,30.3 71.4,31.8 67.1,31.8 67,31.9 67,42.9 49.4,42.9 49.4,42.8
S$610
  Bottom 1.016: 73.5,32.9 72.9,32.9 71.8,34 69,34 69,45.5 49.3,45.5 49.3,45.3
S$611  (2 unrouted)
S$612  (2 unrouted)
S$613
  Bottom 1.93: 14.89,94.04 58.9,93.91
S$614  (via drill 1)
  Bottom 1.422: 40.5,96.68 v42.17,96.68
S$615  (via drill 1)
  other vias: 52.35,96.68
S$616  (via drill 1)  (2 unrouted)
  other vias: 62.1,96.6
S$617
  Bottom 1.422: 49.88,96.68 51.77,96.68
S$618  (1 unrouted)
S$619  (2 unrouted)
S$620  (via drill 1)
  Bottom 1.422: 20.13,96.7 19.43,96.93 v21.97,96.93
  other vias: 3.27,86.33
S$621  (via drill 1)
  other vias: 31.82,96.58
S$622
  Bottom 1.422: 29.78,96.58 31.94,96.58
S$623  (2 unrouted)
S$624  (2 unrouted)
S$626  (2 unrouted)
S$627  (via drill 1)
  other vias: 3.32,65.2 3.32,75.8
S$628
  Bottom 1.93: 6.1,84.8 6,55.7
S$629
  Bottom 1.422: 3.3,83.6 3.3,86.3
S$630
  Bottom 1.422: 3.4,73.4 3.3,75.4
S$631
  Bottom 1.422: 3.3,62.5 3.3,65.2
S$632
  Bottom 1.016: 58.5,12 58.9,12 58.9,18 52.6,18 52.6,18.3 52.5,18.3 52.5,23.5 46,23.5 46,47.8 71,47.8 71,41.8 71.2,41.6 75.8,41.6
S$633  (1 unrouted)
  Bottom 1.016: 13.5,84.4 13.5,84.3
S$634  (1 unrouted)
  Bottom 1.016: 13.8,74.3 13.8,74.4
S$635  (1 unrouted)
S$636  (1 unrouted)
  Bottom 1.016: 13.8,79.3 13.7,79.2 13.7,79.3
S$637  (1 unrouted)
  Bottom 1.016: 13.6,69.3 13.5,68.6 | 13.5,68.6 13.6,69 | 11.5,68.6 13.5,68.6
S$638  (1 unrouted)
S$639
  Bottom 1.93: 15.2,94 6.1,94 6.1,84.3
S$649  (4 unrouted)
S$650  (4 unrouted)
S$655  (2 unrouted)
S$656  (2 unrouted)
S$665
  Bottom 1.93: 58.7,93.9 66.4,93.9 66.4,98.2
S$666  (10 unrouted)
  Bottom 0.813: 11.2,57.8 11.3,63.3 11.3,88.3 61.5,88.3 62.4,87.2 62.4,85.8 61.1,84.3 | 60.9,84.1 56.3,79.2
  Bottom 1.016: 63,51.3 65.7,54
S$667  (3 unrouted)
S$668  (4 unrouted)
S$669  (8 unrouted)
S$670  (10 unrouted)
S$671  (6 unrouted)
  Bottom 1.016: 20.6,86.6 20.6,85.7
S$672  (4 unrouted)
S$673  (3 unrouted)
S$674  (1 unrouted)
S$675  (2 unrouted)
S$676  (5 unrouted)
S$677  (8 unrouted)
S$679  (8 unrouted)
S$680  (1 unrouted)
S$681  (1 unrouted)
  Bottom 1.016: 66.1,87.6 71.5,87.6
S$682  (10 unrouted)
  Bottom 1.016: 71.2,84.9 66.2,84.9
S$683  (2 unrouted)
S$684  (14 unrouted)
S$685  (1 unrouted)
S$686  (7 unrouted)
S$687  (6 unrouted)
S$688  (1 unrouted)
S$689  (1 unrouted)
S$690  (7 unrouted)
S$691  (3 unrouted)
S$692  (2 unrouted)
S$693  (2 unrouted)
S$694  (7 unrouted)
S$696  (1 unrouted)
S$698  (2 unrouted)
S$699  (1 unrouted)
S$703  (1 unrouted)
S$705  (3 unrouted)
S$706  (2 unrouted)
S$707  (1 unrouted)
S$709  (1 unrouted)
S$710  (7 unrouted)
S$712  (1 unrouted)
S$714  (1 unrouted)
S$716  (1 unrouted)
S$717  (1 unrouted)
S$718  (1 unrouted)
S$719  (2 unrouted)
S$720  (2 unrouted)
S$721  (9 unrouted)
S$722
  Bottom 1.016: 75,56.9 76,56.8 80.1,56.8 80.1,60.7
S$723
  Bottom 1.016: 74.9,51.8 78.2,51.8 78.2,40.3 80.2,38.6
S$724
  Bottom 1.016: 75.5,54.3 80.3,54.3 80.3,41.2
S$725
  Bottom 1.016: 80.2,41.2 82,39.6
S$726  (2 unrouted)
  Bottom 1.016: 118.3,52.1 118.2,52.1
S$727  (via drill 1)  (5 unrouted)
  other vias: 71.2,61.4 71.2,64 86.8,61.4
S$729  (1 unrouted)
  Bottom 1.016: 86.3,35.4 89.1,35.4 89.1,63.6
S$730  (via drill 1)
  other vias: 89.1,63.3
S$732  (via drill 1)
  other vias: 84.8,65.1
S$733  (via drill 1)
  other vias: 83.5,62.4
S$734  (via drill 1)
  other vias: 72.8,36.1
S$735  (via drill 1)
  Bottom 1.016: v75.5,38.6 76.4,38.6 78.1,36.9
S$736
  Top 0.406: 83.6,62.3 79.3,62.3 79.4,38.6 75.2,38.6
S$738  (1 unrouted)
S$749  (via drill 1.2)
  other vias: 25.9,51.6
S$750  (via drill 1.2)
  other vias: 23.3,51.6
S$751  (via drill 1.2)
  other vias: 20.6,51.6
S$752  (via drill 1.2)
  other vias: 17.8,51.6
S$753  (via drill 1.2)
  other vias: 15,51.6
S$754  (via drill 1.2)
  other vias: 12.4,51.6
S$755  (via drill 1.2)
  other vias: 3.7,11
S$756  (via drill 1.2)
  other vias: 3.7,7.7
S$757  (via drill 1.2)
  other vias: 7.2,96
S$758  (via drill 1.2)
  other vias: 10.5,96
S$759  (via drill 1.2)
  other vias: 155.9,92.4
S$760  (via drill 1.2)
  other vias: 155.9,89.1
S$763  (via drill 1.2)
  other vias: 89.1,57.8
S$764  (via drill 1.2)
  other vias: 86.8,60.1
S$765  (via drill 1.2)
  other vias: 86.4,64.5
S$766  (via drill 1.2)
  other vias: 83.5,60.9
S$767  (via drill 1.2)
  other vias: 80,58.8
S$768  (1 unrouted)
  Bottom 1.016: 74.6,56.9 75.9,56.9
S$769
  Bottom 1.016: 73.8,63.9 71.1,63.9
S$770
  Bottom 1.016: 71,61.5 75.9,61.6
S$771
  Bottom 1.016: 83.9,61.7 82.6,61.7
S$772
  Bottom 1.016: 85.5,65.1 83.9,65.1
S$773
  Bottom 0.406: 0,4.1 0,0 6.8,0
S$774
  Bottom 0.406: 160.2,12.2 160.2,0 149.5,0 149.5,-0.2
S$775
  Bottom 0.406: 148.4,100 160.3,100 160.3,100.1 | 160.3,100.2 160.3,100.1 | 160.3,100.1 160.2,100.1 160.2,91.3
VCC  (10 unrouted)
  Bottom 1.016: 170.53,50.84 202.25,50.95 206.68,48.42 IC1.10
(copper drawn outside any net)
  shapes: Bottom area x6

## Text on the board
Bottom: 11/2011 | V1 | 11/2011 | GND | VCC | 11/2011 | V1
tTest: GND | LCD BGL VCC | LCD VCC | LED + G - Laden | LED + R - Entladen | LCD DB4 | LCD DB5 | LCD DB6 | LCD DB7 | LCD RS | LCD E | LCD BGL GND | GND | LCD Kontrast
